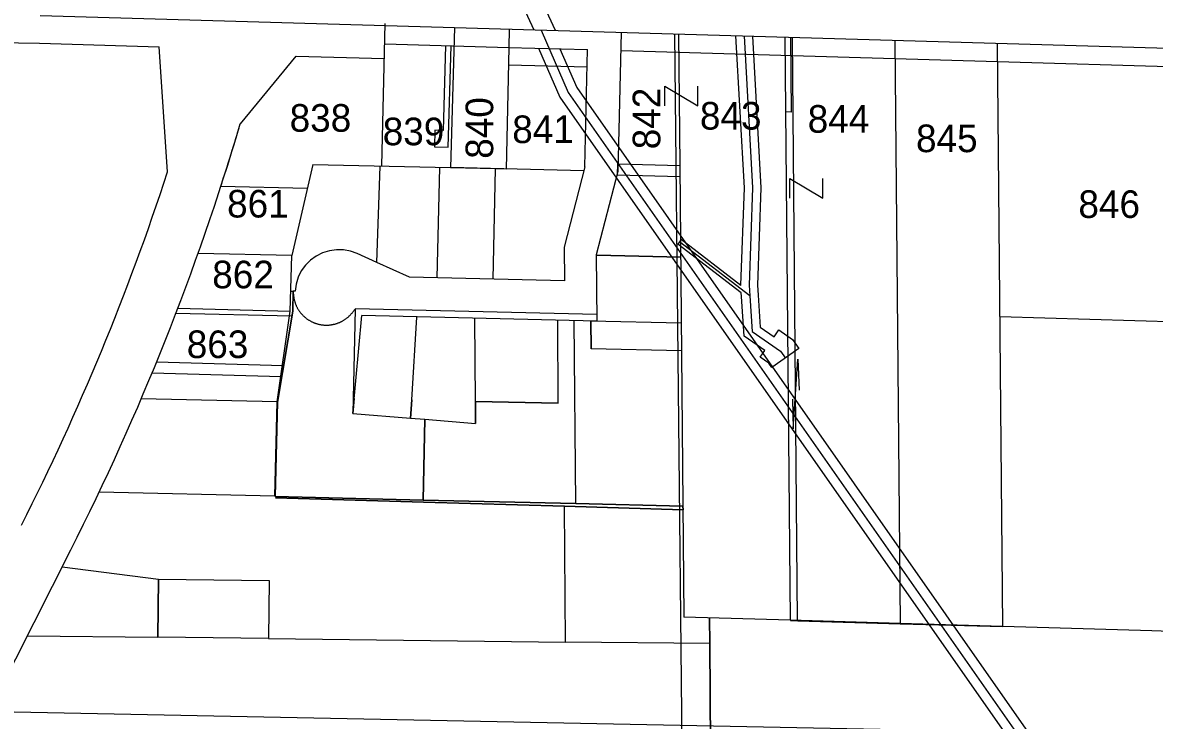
# Model space of a CAD drawing. Extents: x 582596 to 627039, y 145946 to 197316.
# Drawn here: x 617809 to 619859, y 163403 to 164667 of the extents above; entities that cross this region are included whole.
import ezdxf

# ---------------------------------------------------------------- set-up
doc = ezdxf.new("R2010")
doc.units = 0
for name, color, linetype in [('Defpoints 2', 7, 'Continuous'), ('E_RW_EasementUtility', 7, 'Continuous'), ('E_RW_Existing', 7, 'Continuous'), ('E_RW_SixteenthLine', 7, 'Continuous'), ('P_RW_MinorLotLine', 7, 'Continuous'), ('P_RW_PropertyConnector', 7, 'Continuous'), ('P_RW_PropertyLine', 7, 'Continuous'), ('P_RW_SectionLine', 7, 'Continuous')]:
    doc.layers.add(name, color=color, linetype=linetype)

msp = doc.modelspace()

# ---------------------------------------------------------------- linework, layer by layer
at = {"layer": 'E_RW_EasementUtility'}
for p, q in [((618774.7, 164652.4), (618571.7, 165092.8)), ((618539.3, 165079.5), (618735.6, 164653.6)), ((618748.9, 164653.2), (618797.8, 164540.3)), ((618748.9, 164653.2), (618797.8, 164540.3)), ((618575.7, 164625.2), (618571.3, 164471.2)), ((618580.4, 164440.9), (618585.7, 164624.9)), ((619200.2, 164640.1), (619201.4, 164504.8)), ((619200.2, 164640.1), (619201.4, 164504.8)), ((618744.1, 164620.3), (618782.4, 164531.7)), ((618744.1, 164620.3), (618782.4, 164531.7)), ((618782.7, 164619.2), (618813.1, 164548.9)), ((618782.7, 164619.2), (618813.1, 164548.9)), ((618832, 164585.7), (618689.4, 164589.9)), ((618797.8, 164540.3), (619844.8, 163045.5)), ((618797.8, 164540.3), (619844.8, 163045.5)), ((618813.1, 164548.9), (619857.5, 163057.8)), ((618813.1, 164548.9), (619857.5, 163057.8)), ((618782.4, 164531.7), (619832, 163033.2)), ((618782.4, 164531.7), (619832, 163033.2)), ((619201.4, 164504.8), (619191.4, 164505.1)), ((619201.4, 164504.8), (619191.4, 164505.1)), ((618556.3, 164471.7), (618555.4, 164441.7)), ((618571.3, 164471.2), (618556.3, 164471.7)), ((618555.4, 164441.7), (618580.4, 164440.9)), ((619002.2, 164273.7), (618996.2, 164265.7)), ((619002.2, 164273.7), (618996.2, 164265.7)), ((619110.3, 164190.8), (619002.2, 164273.7)), ((619110.3, 164190.8), (619002.2, 164273.7)), ((619111.2, 164177.5), (618996.2, 164265.7)), ((619111.2, 164177.5), (618996.2, 164265.7)), ((619126.6, 164172), (618999.2, 164269.7)), ((619126.6, 164172), (618999.2, 164269.7)), ((618296.7, 164134.9), (618086.8, 164139.8)), ((618281.4, 164045.3), (618052, 164052)), ((618278, 164025.4), (618043.9, 164032.2))]:
    msp.add_line(p, q, dxfattribs=at)
for points in [[(619110.3, 164190.8), (619110.3, 164191.1), (619116.8, 164367.5), (619101.3, 164643)], [(619110.3, 164190.8), (619110.3, 164191.1), (619116.8, 164367.5), (619101.3, 164643)], [(619131.4, 164642.1), (619146.8, 164367.8), (619140.3, 164191.5), (619141.6, 164173), (619145.4, 164115.5), (619170.8, 164097.9), (619179.3, 164110.3), (619204, 164093.2), (619215.7, 164076.7), (619166.7, 164042), (619161.1, 164049.9), (619145.2, 164060.9), (619153.7, 164073.3), (619116.4, 164099.1), (619111.6, 164171), (619111.2, 164177.5)], [(619131.4, 164642.1), (619146.8, 164367.8), (619140.3, 164191.5), (619141.6, 164173), (619145.4, 164115.5), (619170.8, 164097.9), (619179.3, 164110.3), (619204, 164093.2), (619215.7, 164076.7), (619166.7, 164042), (619161.1, 164049.9), (619145.2, 164060.9), (619153.7, 164073.3), (619116.4, 164099.1), (619111.6, 164171), (619111.2, 164177.5)], [(619116.4, 164642.6), (619131.8, 164367.7), (619125.3, 164191.3), (619126.6, 164172), (619130.9, 164107.3), (619182.5, 164071.6), (619191.2, 164059.3)], [(619116.4, 164642.6), (619131.8, 164367.7), (619125.3, 164191.3), (619126.6, 164172), (619130.9, 164107.3), (619182.5, 164071.6), (619191.2, 164059.3)]]:
    msp.add_lwpolyline(points, dxfattribs=at)
at = {"layer": 'E_RW_Existing'}
for p, q in [((617664.8, 164632.7), (617839.7, 164629.4)), ((617839.7, 164629.4), (618056.7, 164623.1)), ((618072, 164396.4), (618056.7, 164623.1)), ((618465.8, 164628.3), (618690.1, 164621.9)), ((618893.8, 164616), (619575.4, 164596.3)), ((619575.4, 164596.3), (619984.8, 164584.4))]:
    msp.add_line(p, q, dxfattribs=at)
msp.add_arc((613762.4, 165804.5), 4533.8, 333.1534, 341.9052, dxfattribs=at)
at = {"layer": 'E_RW_SixteenthLine'}
for p, q in [((619018.2, 162063.3), (618990.6, 164646.2)), ((617679.6, 163421.2), (620328.3, 163368.3))]:
    msp.add_line(p, q, dxfattribs=at)
at = {"layer": 'P_RW_MinorLotLine'}
for p, q in [((618997.5, 164646), (618999.7, 164407.8)), ((619213.3, 163584.1), (619203.7, 164640)), ((619213.3, 163584.1), (619203.7, 164640)), ((618887.1, 164391.1), (618887.7, 164411.1)), ((618887.1, 164391.1), (618999.9, 164387.8)), ((619205, 163931.1), (619213.8, 164057.3)), ((619205, 163931.1), (619213.8, 164057.3)), ((619213.8, 164057.3), (619215.9, 164001)), ((619213.8, 164057.3), (619215.9, 164001)), ((619203.8, 163984.9), (619205, 163931.1)), ((619203.8, 163984.9), (619205, 163931.1))]:
    msp.add_line(p, q, dxfattribs=at)
at = {"layer": 'P_RW_PropertyConnector'}
for p, q in [((618972.6, 164516.1), (618972.6, 164551.7)), ((618972.6, 164551.7), (619032.6, 164516.1)), ((619032.6, 164516.1), (619032.6, 164551.7)), ((619002.6, 164533.9), (619002.6, 164533.9)), ((619198.9, 164349), (619198.9, 164384.6)), ((619198.9, 164384.6), (619258.9, 164349)), ((619258.9, 164349), (619258.9, 164384.6)), ((619228.9, 164366.8), (619228.9, 164366.8))]:
    msp.add_line(p, q, dxfattribs=at)
at = {"layer": 'P_RW_PropertyLine'}
for p, q in [((618465.7, 164665), (618459.7, 164407.1)), ((618591.7, 164657.7), (618584.3, 164403.7)), ((618690.9, 164654.8), (618690.1, 164621.9)), ((618893.5, 164649), (618887.6, 164397.1)), ((618690.1, 164621.9), (618685.3, 164401.6)), ((618689.8, 164621.9), (618832.7, 164617.7)), ((619190.2, 164640.4), (619199.8, 163584.5)), ((619389.2, 164634.7), (619398.9, 163578.7)), ((619574.8, 164629.3), (619584.4, 163573.3)), ((618203.8, 164483.2), (618304.9, 164606)), ((618304.9, 164606), (618464.2, 164601.4)), ((618827.8, 164405.3), (618832.7, 164617.7)), ((618335.2, 164410), (618296.9, 164245)), ((618335.2, 164410), (618584.7, 164404.1)), ((618451, 164232.5), (618457.1, 164406.9)), ((618560.4, 164204.4), (618565, 164404.3)), ((618665.3, 164402), (618584.3, 164403.7)), ((618826, 164398.4), (618584.7, 164404.1)), ((618665.3, 164402), (618661, 164202.1)), ((618685.3, 164401.6), (618665.3, 164402)), ((618827.8, 164405.3), (618790.2, 164260.3)), ((618887.6, 164397.1), (618848.5, 164246.2)), ((618887.7, 164411.1), (618999.7, 164407.8)), ((618999.7, 164407.8), (619007.2, 163590)), ((618325.1, 164366.3), (618168.4, 164370)), ((618365.1, 164253.7), (618352.8, 164249.8)), ((618377.9, 164255.4), (618365.1, 164253.7)), ((618390.8, 164255.2), (618377.9, 164255.4)), ((618403.5, 164252.8), (618390.8, 164255.2)), ((618415.6, 164248.5), (618403.5, 164252.8)), ((618790.2, 164260.3), (618790.8, 164199.3)), ((618296.9, 164245), (618127.3, 164248.9)), ((618294.3, 164144.1), (618296.9, 164245)), ((618330.8, 164236.6), (618321.7, 164227.4)), ((618341.3, 164244.1), (618330.8, 164236.6)), ((618352.8, 164249.8), (618341.3, 164244.1)), ((618451, 164232.5), (618415.6, 164248.5)), ((618510.5, 164205.6), (618451, 164232.5)), ((618848.5, 164246.2), (618849.7, 164126.2)), ((619001.5, 164242.2), (618849.5, 164245.7)), ((618849.5, 164245.7), (619001.5, 164242.2)), ((618314.2, 164217), (618308.4, 164205.5)), ((618321.7, 164227.4), (618314.2, 164217)), ((618304.6, 164193.2), (618302.8, 164180.4)), ((618308.4, 164205.5), (618304.6, 164193.2)), ((618790.8, 164199.3), (618510.4, 164205.9)), ((618295.8, 164180.6), (618299.7, 164180.5)), ((618298.9, 164144.3), (618299.7, 164180.5)), ((618299.7, 164180.5), (618298.9, 164144.3)), ((618299.7, 164180.5), (618299.7, 164178.2)), ((618302.8, 164180.4), (618299.7, 164180.5)), ((618299.7, 164178.2), (618299.7, 164177.2)), ((618299.7, 164177.2), (618299.7, 164176.1)), ((618299.7, 164176.1), (618299.8, 164175.1)), ((618299.8, 164175.1), (618299.9, 164174)), ((618299.9, 164174), (618300, 164173)), ((618300, 164173), (618300.1, 164172)), ((618300.1, 164172), (618300.2, 164170.9)), ((618300.2, 164170.9), (618300.4, 164169.9)), ((618090.7, 164149.9), (618294.3, 164144.1)), ((618300.4, 164169.9), (618300.5, 164168.8)), ((618300.5, 164168.8), (618300.7, 164167.8)), ((618300.7, 164167.8), (618300.9, 164166.8)), ((618300.9, 164166.8), (618301.1, 164165.8)), ((618301.1, 164165.8), (618301.4, 164164.7)), ((618301.4, 164164.7), (618301.6, 164163.7)), ((618301.6, 164163.7), (618301.9, 164162.7)), ((618301.9, 164162.7), (618302.2, 164161.7)), ((618302.2, 164161.7), (618302.5, 164160.7)), ((618302.5, 164160.7), (618302.8, 164159.7)), ((618302.8, 164159.7), (618303.2, 164158.7)), ((618303.2, 164158.7), (618303.5, 164157.7)), ((618303.5, 164157.7), (618303.9, 164156.8)), ((618303.9, 164156.8), (618304.3, 164155.8)), ((618304.3, 164155.8), (618304.7, 164154.8)), ((618304.7, 164154.8), (618305.1, 164153.9)), ((618305.1, 164153.9), (618305.6, 164152.9)), ((618305.6, 164152.9), (618306.1, 164152)), ((618306.1, 164152), (618306.5, 164151.1)), ((618306.5, 164151.1), (618307, 164150.1)), ((618307, 164150.1), (618307.5, 164149.2)), ((618270.3, 163980), (618294.3, 164144.1)), ((618270.8, 163979.4), (618298.9, 164144.3)), ((618298.9, 164144.3), (618270.8, 163979.4)), ((618307.5, 164149.2), (618308.1, 164148.3)), ((618308.1, 164148.3), (618308.6, 164147.4)), ((618308.6, 164147.4), (618309.2, 164146.5)), ((618309.2, 164146.5), (618309.7, 164145.7)), ((618309.7, 164145.7), (618310.3, 164144.8)), ((618310.3, 164144.8), (618310.9, 164143.9)), ((618310.9, 164143.9), (618311.5, 164143.1)), ((618311.5, 164143.1), (618312.2, 164142.3)), ((618312.2, 164142.3), (618312.8, 164141.4)), ((618312.8, 164141.4), (618313.5, 164140.6)), ((618313.5, 164140.6), (618314.2, 164139.8)), ((618314.2, 164139.8), (618314.9, 164139)), ((618314.9, 164139), (618315.6, 164138.3)), ((618315.6, 164138.3), (618316.3, 164137.5)), ((618316.3, 164137.5), (618317, 164136.7)), ((618317, 164136.7), (618317.7, 164136)), ((618317.7, 164136), (618318.5, 164135.3)), ((618318.5, 164135.3), (618319.3, 164134.6)), ((618319.3, 164134.6), (618320, 164133.9)), ((618320, 164133.9), (618320.8, 164133.2)), ((618320.8, 164133.2), (618321.6, 164132.5)), ((618321.6, 164132.5), (618322.5, 164131.9)), ((618322.5, 164131.9), (618323.3, 164131.2)), ((618323.3, 164131.2), (618324.1, 164130.6)), ((618324.1, 164130.6), (618325, 164130)), ((618325, 164130), (618325.8, 164129.4)), ((618325.8, 164129.4), (618326.7, 164128.8)), ((618392.9, 164129), (618393.8, 164129.6)), ((618393.8, 164129.6), (618394.7, 164130.2)), ((618394.7, 164130.2), (618395.5, 164130.8)), ((618395.5, 164130.8), (618396.3, 164131.4)), ((618396.3, 164131.4), (618397.2, 164132.1)), ((618397.2, 164132.1), (618398, 164132.7)), ((618398, 164132.7), (618398.8, 164133.4)), ((618398.8, 164133.4), (618399.6, 164134.1)), ((618399.6, 164134.1), (618400.3, 164134.8)), ((618400.3, 164134.8), (618401.1, 164135.5)), ((618401.1, 164135.5), (618401.9, 164136.2)), ((618401.9, 164136.2), (618402.6, 164137)), ((618402.6, 164137), (618403.3, 164137.7)), ((618403.3, 164137.7), (618404, 164138.5)), ((618404, 164138.5), (618404.7, 164139.3)), ((618404.7, 164139.3), (618405.4, 164140.1)), ((618405.4, 164140.1), (618406.1, 164140.9)), ((618406.1, 164140.9), (618406.7, 164141.7)), ((618406.7, 164141.7), (618407.4, 164142.5)), ((618407.4, 164142.5), (618408, 164143.4)), ((618411.9, 164147.7), (618407.6, 163959.2)), ((618407.6, 163959.2), (618423.7, 164136.1)), ((618408, 164143.4), (618408.6, 164144.2)), ((618408.6, 164144.2), (618409.2, 164145.1)), ((618409.2, 164145.1), (618409.8, 164145.9)), ((618409.8, 164145.9), (618410.4, 164146.8)), ((618410.4, 164146.8), (618410.9, 164147.7)), ((618410.9, 164147.7), (618411.9, 164147.7)), ((618849.6, 164137.9), (618412, 164148.2)), ((618849.7, 164126.2), (618423.7, 164136.1)), ((618514.2, 163983.4), (618523.7, 164133.5)), ((618629.5, 163980.9), (618628.7, 164131)), ((619579.3, 164134.3), (619988.6, 164122.5)), ((618326.7, 164128.8), (618327.6, 164128.2)), ((618327.6, 164128.2), (618328.5, 164127.7)), ((618328.5, 164127.7), (618329.4, 164127.1)), ((618329.4, 164127.1), (618330.3, 164126.6)), ((618330.3, 164126.6), (618331.2, 164126.1)), ((618331.2, 164126.1), (618332.1, 164125.6)), ((618332.1, 164125.6), (618333.1, 164125.1)), ((618333.1, 164125.1), (618334, 164124.7)), ((618334, 164124.7), (618335, 164124.2)), ((618335, 164124.2), (618335.9, 164123.8)), ((618335.9, 164123.8), (618336.9, 164123.4)), ((618336.9, 164123.4), (618337.8, 164123)), ((618337.8, 164123), (618338.8, 164122.7)), ((618338.8, 164122.7), (618339.8, 164122.3)), ((618339.8, 164122.3), (618340.8, 164122)), ((618340.8, 164122), (618341.8, 164121.6)), ((618341.8, 164121.6), (618342.8, 164121.3)), ((618342.8, 164121.3), (618343.8, 164121.1)), ((618343.8, 164121.1), (618344.8, 164120.8)), ((618344.8, 164120.8), (618345.8, 164120.5)), ((618345.8, 164120.5), (618346.9, 164120.3)), ((618346.9, 164120.3), (618347.9, 164120.1)), ((618347.9, 164120.1), (618348.9, 164119.9)), ((618348.9, 164119.9), (618349.9, 164119.7)), ((618349.9, 164119.7), (618351, 164119.5)), ((618351, 164119.5), (618352, 164119.4)), ((618352, 164119.4), (618353.1, 164119.3)), ((618353.1, 164119.3), (618354.1, 164119.2)), ((618354.1, 164119.2), (618355.1, 164119.1)), ((618355.1, 164119.1), (618356.2, 164119)), ((618356.2, 164119), (618357.2, 164119)), ((618357.2, 164119), (618358.3, 164118.9)), ((618358.3, 164118.9), (618359.3, 164118.9)), ((618359.3, 164118.9), (618360.4, 164118.9)), ((618360.4, 164118.9), (618361.4, 164118.9)), ((618361.4, 164118.9), (618362.5, 164119)), ((618362.5, 164119), (618363.5, 164119)), ((618363.5, 164119), (618364.6, 164119.1)), ((618364.6, 164119.1), (618365.6, 164119.2)), ((618365.6, 164119.2), (618366.6, 164119.3)), ((618366.6, 164119.3), (618367.7, 164119.5)), ((618367.7, 164119.5), (618368.7, 164119.6)), ((618368.7, 164119.6), (618369.7, 164119.8)), ((618369.7, 164119.8), (618370.8, 164120)), ((618370.8, 164120), (618371.8, 164120.2)), ((618371.8, 164120.2), (618372.8, 164120.4)), ((618372.8, 164120.4), (618373.9, 164120.6)), ((618373.9, 164120.6), (618374.9, 164120.9)), ((618374.9, 164120.9), (618375.9, 164121.1)), ((618375.9, 164121.1), (618376.9, 164121.4)), ((618376.9, 164121.4), (618377.9, 164121.7)), ((618377.9, 164121.7), (618378.9, 164122.1)), ((618378.9, 164122.1), (618379.9, 164122.4)), ((618379.9, 164122.4), (618380.9, 164122.8)), ((618380.9, 164122.8), (618381.8, 164123.2)), ((618381.8, 164123.2), (618382.8, 164123.5)), ((618382.8, 164123.5), (618383.8, 164124)), ((618383.8, 164124), (618384.7, 164124.4)), ((618384.7, 164124.4), (618385.7, 164124.8)), ((618385.7, 164124.8), (618386.6, 164125.3)), ((618386.6, 164125.3), (618387.5, 164125.8)), ((618387.5, 164125.8), (618388.5, 164126.3)), ((618388.5, 164126.3), (618389.4, 164126.8)), ((618389.4, 164126.8), (618390.3, 164127.3)), ((618390.3, 164127.3), (618391.2, 164127.8)), ((618391.2, 164127.8), (618392.1, 164128.4)), ((618392.1, 164128.4), (618392.9, 164129)), ((618779.4, 163977.4), (618778.7, 164127.4)), ((618811.6, 163795.9), (618808.6, 164126.7)), ((619002.6, 164122.2), (618838.6, 164126)), ((618839.1, 164076), (618838.6, 164126)), ((618838.6, 164126), (618839.1, 164076)), ((619003.1, 164072.2), (618839.1, 164076)), ((618270.3, 163980), (618024.3, 163985.7)), ((618407.6, 163959.2), (618410, 163985.8)), ((618410, 163985.8), (618407.6, 163959.2)), ((618266.3, 163809.2), (618270.3, 163980)), ((618266.8, 163808.6), (618270.8, 163979.4)), ((618270.8, 163979.4), (618266.8, 163808.6)), ((618512.2, 163950.7), (618514.2, 163983.4)), ((618514.2, 163983.4), (618512.2, 163950.7)), ((618629.8, 163940.9), (618629.5, 163980.9)), ((618629.5, 163980.9), (618779.4, 163977.4)), ((618779.4, 163977.4), (618629.5, 163980.9)), ((618629.5, 163980.9), (618629.8, 163940.9)), ((618407.6, 163959.2), (618512.2, 163950.7)), ((618512.2, 163950.7), (618538.2, 163948.5)), ((618538.2, 163948.5), (618534.8, 163802.3)), ((618534.8, 163802.3), (618538.2, 163948.5)), ((618538.2, 163948.5), (618629.8, 163940.9)), ((618266.3, 163809.2), (617948.1, 163816.6)), ((618534.8, 163802.3), (618266.8, 163808.6)), ((618266.8, 163808.6), (618534.8, 163802.3)), ((618267.4, 163806.1), (618535.4, 163798.3)), ((618535.4, 163798.3), (618267.4, 163806.1)), ((618811.6, 163795.9), (618534.8, 163802.3)), ((618534.8, 163802.3), (618811.6, 163795.9)), ((618535.4, 163798.3), (618790.8, 163791)), ((618790.8, 163791), (618535.4, 163798.3)), ((618792.9, 163545.2), (618790.8, 163791)), ((618790.8, 163791), (619005.7, 163784.8)), ((619005.7, 163784.8), (618790.8, 163791)), ((619005.6, 163791.3), (618811.6, 163795.9)), ((618811.6, 163795.9), (619005.6, 163791.3)), ((619005.7, 163784.8), (619005.6, 163791.3)), ((619005.6, 163791.3), (619005.7, 163784.8)), ((617586.5, 163099), (617896.8, 163711.9)), ((617881.3, 163681.3), (618055.7, 163658.7)), ((618054.6, 163553.7), (618055.7, 163658.7)), ((618055.7, 163658.7), (618054.6, 163553.7)), ((618055.7, 163658.7), (618255.7, 163656.4)), ((618255.7, 163656.4), (618254.5, 163551.4)), ((619199.8, 163584.5), (619007.2, 163590)), ((619199.8, 163584.5), (619007.2, 163590)), ((619053.6, 163588.3), (619054, 163542.3)), ((619054, 163542.3), (619053.6, 163588.3)), ((619398.9, 163578.7), (619199.8, 163584.5)), ((619398.9, 163578.7), (619199.8, 163584.5)), ((619213.6, 163583.7), (619200.1, 163584.1)), ((619200.1, 163584.1), (619213.6, 163583.7)), ((619399.2, 163578.3), (619213.6, 163583.7)), ((619213.6, 163583.7), (619399.2, 163578.3)), ((619584.4, 163573.3), (619398.9, 163578.7)), ((619584.7, 163573), (619399.2, 163578.3)), ((619399.2, 163578.3), (619584.7, 163573)), ((617818.1, 163556.5), (618054.6, 163553.7)), ((617828.8, 163555.9), (617829, 163556.3)), ((619854.6, 163565.2), (619584.7, 163573)), ((620326.9, 163551.5), (619854.6, 163565.2)), ((618254.5, 163551.4), (618054.6, 163553.7)), ((618254.5, 163551.4), (618792.9, 163545.2)), ((619054, 163542.3), (618792.9, 163545.2)), ((619055.6, 163345.1), (619054, 163542.3)), ((619054, 163542.3), (619055.6, 163345.1))]:
    msp.add_line(p, q, dxfattribs=at)
for centre, start, end in [((613762.4, 165804.5), 333.1534, 343.4321), ((613763.6, 165808.6), 341.9131, 343.3812)]:
    msp.add_arc(centre, 4633.7, start, end, dxfattribs=at)
at = {"layer": 'P_RW_SectionLine'}
msp.add_line((617840.9, 164679.4), (620478.6, 164603.2), dxfattribs=at)

# ---------------------------------------------------------------- texts
at = {"layer": 'Defpoints 2'}
for s, p in [('842', (618964.5, 164437.3)), ('840', (618661.8, 164420.1))]:
    msp.add_text(s, height=50, rotation=90, dxfattribs=at).set_placement(p)
for s, p in [('838', (618293.1, 164469.1)), ('843', (619036.3, 164473)), ('841', (618696.3, 164448.5)), ('844', (619231.5, 164467.3)), ('839', (618461.7, 164444.6)), ('845', (619427.7, 164432.1)), ('861', (618179.8, 164313.8)), ('846', (619721.9, 164313)), ('862', (618152.9, 164185.6)), ('863', (618106.7, 164059.3))]:
    msp.add_text(s, height=50, dxfattribs=at).set_placement(p)

doc.saveas('drawing.dxf')
